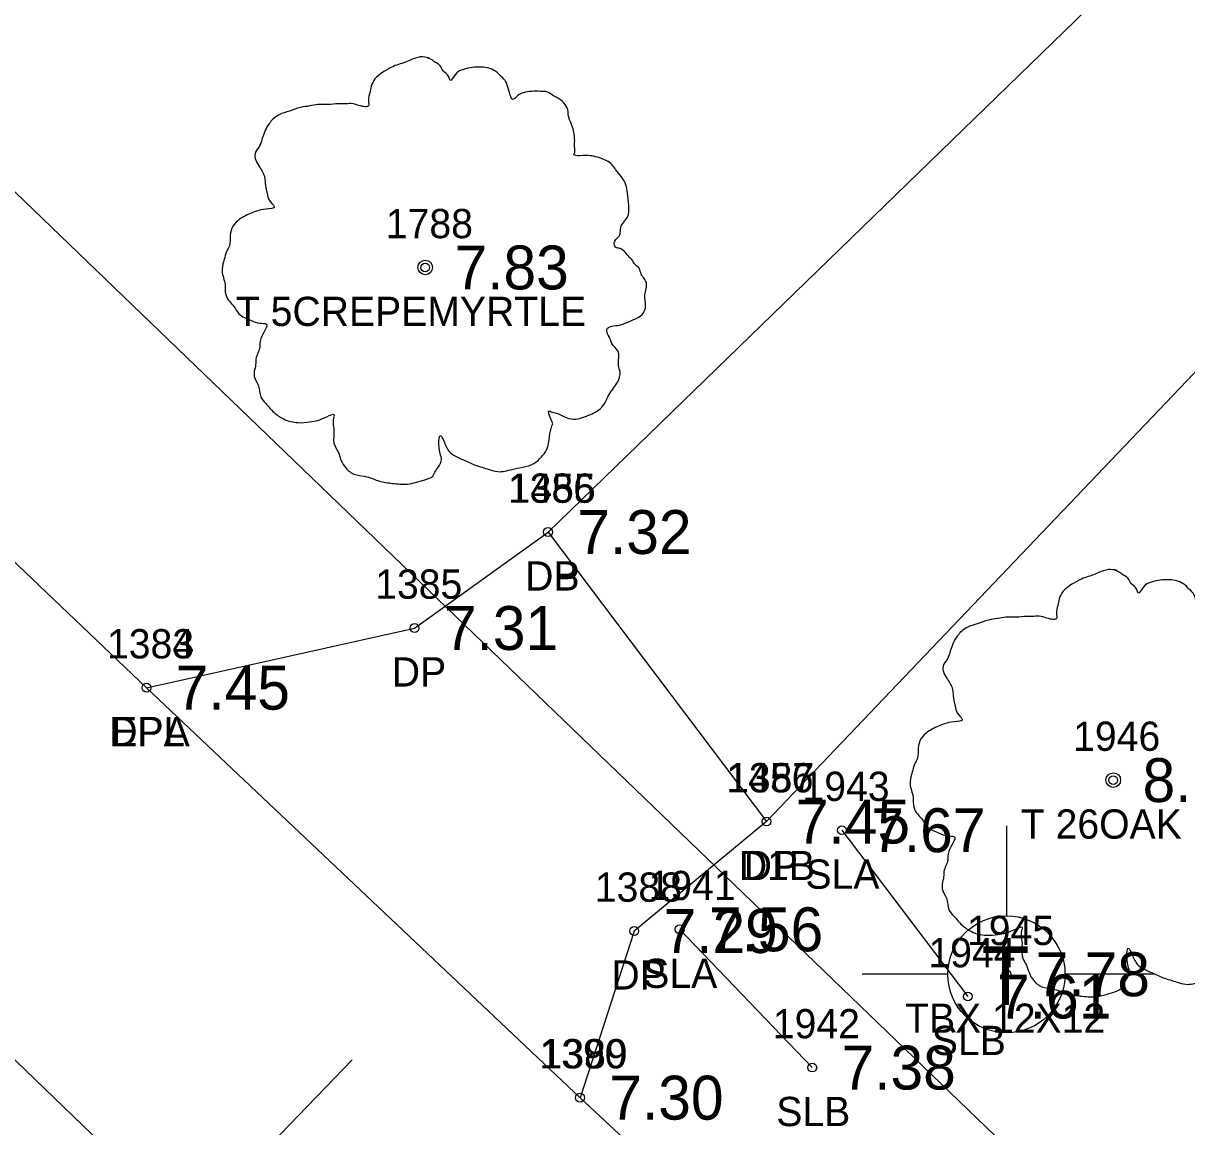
# Model space of a CAD drawing. Extents: x 2608598 to 2610682, y 641451 to 643526.
# Drawn here: x 2609158.19 to 2609197.94, y 643040.35 to 643078.05 of the extents above; entities that cross this region are included whole.
import ezdxf

# ---------------------------------------------------------------- set-up
doc = ezdxf.new("R2010")
doc.units = 0
for name, color, linetype in [('RD_EX_DR_Pipe', 7, 'Continuous'), ('RD_EX_Driveway', 7, 'Continuous'), ('RD_EX_Driveway_txCode', 7, 'Continuous'), ('RD_EX_Road', 7, 'Continuous'), ('RD_EX_Road_txCode', 7, 'Continuous'), ('RD_EX_TX_Driveway_ELEV', 7, 'Continuous'), ('RD_EX_TX_Road_ELEV', 7, 'Continuous'), ('RD_EX_TX_UT_ELEV', 7, 'Continuous'), ('RD_EX_TX_VEG_ELEV', 7, 'Continuous'), ('RD_EX_UT', 7, 'Continuous'), ('RD_EX_UT_txCode', 7, 'Continuous'), ('RD_EX_VEG', 7, 'Continuous'), ('RD_EX_VEG_txCode', 7, 'Continuous'), ('RD_HC_Cl', 7, 'Continuous'), ('RD_HC_Data_Tic', 7, 'Continuous'), ('RD_SMD_Locator', 7, 'Continuous')]:
    doc.layers.add(name, color=color, linetype=linetype)

msp = doc.modelspace()

# ---------------------------------------------------------------- linework, layer by layer
at = {"layer": 'RD_EX_DR_Pipe'}
msp.add_line((2609069.044, 643157.849), (2609202.653, 643029.203), dxfattribs=at)
at = {"layer": 'RD_EX_Driveway'}
for points in [[(2609166.457, 643161.041), (2609160.17, 643148.257), (2609190.362, 643122.83), (2609213.317, 643102.873), (2609223.768, 643094.8), (2609208.755, 643077.174), (2609183.581, 643050.775)], [(2609100.57, 643145.923), (2609122.94, 643140.66), (2609155.044, 643137.099), (2609182.051, 643117.558), (2609202.041, 643097.354), (2609199.499, 643083.361), (2609176.116, 643060.669)], [(2609162.396, 643055.351), (2609171.558, 643057.39), (2609176.116, 643060.669), (2609183.581, 643050.775), (2609179.063, 643047.036), (2609177.209, 643041.342)]]:
    msp.add_lwpolyline(points, dxfattribs=at)
at = {"layer": 'RD_EX_Road'}
msp.add_lwpolyline([(2609042.495, 643170.94), (2609058.512, 643155.458), (2609096.06, 643119.372), (2609116.51, 643099.11), (2609162.396, 643055.351), (2609177.209, 643041.342), (2609188.353, 643030.959), (2609199.912, 643019.764), (2609205.803, 643014.044), (2609217.132, 643003.172), (2609235.835, 642983.899), (2609237.032, 642983.51), (2609256.803, 642965.042), (2609258.491, 642962.514), (2609263.653, 642957.664), (2609344.713, 642879.888)], dxfattribs=at)
at = {"layer": 'RD_EX_UT'}
for p, q in [((2609191.777, 643050.627), (2609191.777, 643047.558)), ((2609186.847, 643045.573), (2609189.777, 643045.573)), ((2609193.777, 643045.573), (2609196.847, 643045.573))]:
    msp.add_line(p, q, dxfattribs=at)
msp.add_circle((2609191.777, 643045.558), 2, dxfattribs=at)
at = {"layer": 'RD_EX_VEG'}
for p, q in [((2609186.156, 643050.481), (2609190.458, 643044.797)), ((2609180.614, 643047.093), (2609185.144, 643042.37))]:
    msp.add_line(p, q, dxfattribs=at)
for centre, radius in [((2609171.922, 643069.709), 0.25), ((2609171.909, 643069.69), 0.0001), ((2609195.426, 643052.193), 0.25), ((2609195.413, 643052.174), 0.0001)]:
    msp.add_circle(centre, radius, dxfattribs=at)
for points in [[(2609172.054, 643076.876), (2609171.754, 643076.901), (2609171.429, 643076.801), (2609171.179, 643076.702), (2609170.954, 643076.627), (2609170.729, 643076.527), (2609170.43, 643076.352), (2609170.205, 643076.152), (2609170.08, 643075.902), (2609170.03, 643075.677), (2609169.98, 643075.402), (2609169.98, 643075.227), (2609169.855, 643075.202), (2609169.705, 643075.227), (2609169.455, 643075.302), (2609169.205, 643075.302), (2609168.955, 643075.302), (2609168.605, 643075.277), (2609168.256, 643075.277), (2609167.981, 643075.227), (2609167.656, 643075.177), (2609167.281, 643075.052), (2609166.931, 643074.927), (2609166.631, 643074.677), (2609166.381, 643074.203), (2609166.256, 643073.853), (2609166.107, 643073.603), (2609166.256, 643073.153), (2609166.431, 643072.803), (2609166.456, 643072.603), (2609166.531, 643072.179), (2609166.631, 643071.954), (2609166.756, 643071.754), (2609166.681, 643071.729), (2609166.306, 643071.679), (2609166.007, 643071.579), (2609165.582, 643071.354), (2609165.357, 643071.129), (2609165.257, 643070.804), (2609165.232, 643070.454), (2609165.132, 643070.254), (2609165.057, 643069.979), (2609165.032, 643069.904), (2609164.982, 643069.58), (2609165.082, 643069.13), (2609165.107, 643068.78), (2609165.232, 643068.555), (2609165.382, 643068.38), (2609165.557, 643068.13), (2609165.957, 643067.905), (2609166.281, 643067.805), (2609166.481, 643067.78), (2609166.306, 643067.281), (2609166.256, 643066.931), (2609166.132, 643066.531), (2609166.132, 643066.456), (2609166.082, 643065.981), (2609166.231, 643065.656), (2609166.306, 643065.282), (2609166.481, 643065.057), (2609166.756, 643064.757), (2609167.081, 643064.532), (2609167.581, 643064.407), (2609167.981, 643064.432), (2609168.556, 643064.607), (2609168.805, 643064.682), (2609168.78, 643064.507), (2609168.805, 643064.132), (2609168.805, 643063.707), (2609168.955, 643063.382), (2609169.055, 643063.107), (2609169.205, 643062.858), (2609169.53, 643062.633), (2609169.93, 643062.558), (2609170.355, 643062.408), (2609170.805, 643062.333), (2609171.304, 643062.308), (2609171.904, 643062.458), (2609172.179, 643062.583), (2609172.279, 643062.758), (2609172.479, 643063.132), (2609172.429, 643063.357), (2609172.454, 643063.957), (2609172.554, 643063.782), (2609172.729, 643063.432), (2609173.228, 643063.132), (2609173.628, 643062.958), (2609174.103, 643062.808), (2609174.403, 643062.733), (2609174.878, 643062.808), (2609175.253, 643062.883), (2609175.627, 643063.008), (2609175.927, 643063.282), (2609176.102, 643063.557), (2609176.152, 643063.832), (2609176.227, 643064.207), (2609176.277, 643064.382)], [(2609176.277, 643064.382), (2609176.202, 643064.557), (2609176.152, 643064.807), (2609176.227, 643064.782), (2609176.402, 643064.732), (2609176.677, 643064.607), (2609176.902, 643064.532), (2609177.227, 643064.557), (2609177.502, 643064.657), (2609177.951, 643064.932), (2609178.226, 643065.406), (2609178.501, 643065.806), (2609178.576, 643066.131), (2609178.526, 643066.356), (2609178.501, 643066.856), (2609178.301, 643067.106), (2609178.251, 643067.231), (2609178.151, 643067.63), (2609178.226, 643067.68), (2609178.501, 643067.73), (2609178.876, 643067.855), (2609179.151, 643067.98), (2609179.376, 643068.155), (2609179.451, 643068.38), (2609179.426, 643068.78), (2609179.476, 643069.18), (2609179.401, 643069.33), (2609179.301, 643069.48), (2609179.226, 643069.68), (2609179.076, 643069.829), (2609178.976, 643069.979), (2609178.876, 643070.079), (2609178.751, 643070.229), (2609178.576, 643070.354), (2609178.426, 643070.404), (2609178.376, 643070.554), (2609178.526, 643070.754), (2609178.576, 643070.854), (2609178.601, 643071.079), (2609178.826, 643071.429), (2609178.876, 643071.829), (2609178.826, 643072.253), (2609178.776, 643072.528), (2609178.626, 643072.803), (2609178.426, 643073.053), (2609178.301, 643073.228), (2609178.126, 643073.353), (2609177.801, 643073.478), (2609177.552, 643073.528), (2609177.202, 643073.528), (2609177.002, 643073.578), (2609177.027, 643073.628), (2609177.027, 643073.778), (2609177.027, 643074.053), (2609176.952, 643074.502), (2609176.802, 643075.002), (2609176.802, 643075.027), (2609176.702, 643075.277), (2609176.477, 643075.477), (2609176.302, 643075.577), (2609176.102, 643075.702), (2609175.852, 643075.727), (2609175.552, 643075.727), (2609175.277, 643075.677), (2609175.078, 643075.577), (2609174.903, 643075.452), (2609174.828, 643075.602), (2609174.728, 643075.902), (2609174.678, 643076.052), (2609174.528, 643076.227), (2609174.303, 643076.427), (2609173.853, 643076.552), (2609173.228, 643076.477), (2609172.928, 643076.277), (2609172.779, 643076.102), (2609172.729, 643076.227), (2609172.529, 643076.427), (2609172.429, 643076.602), (2609172.254, 643076.727), (2609172.104, 643076.826), (2609172.004, 643076.876)], [(2609195.557, 643059.36), (2609195.258, 643059.385), (2609194.933, 643059.285), (2609194.683, 643059.185), (2609194.458, 643059.11), (2609194.233, 643059.01), (2609193.933, 643058.835), (2609193.708, 643058.635), (2609193.583, 643058.386), (2609193.533, 643058.161), (2609193.483, 643057.886), (2609193.483, 643057.711), (2609193.358, 643057.686), (2609193.208, 643057.711), (2609192.959, 643057.786), (2609192.709, 643057.786), (2609192.459, 643057.786), (2609192.109, 643057.761), (2609191.759, 643057.761), (2609191.484, 643057.711), (2609191.159, 643057.661), (2609190.785, 643057.536), (2609190.435, 643057.411), (2609190.135, 643057.161), (2609189.885, 643056.686), (2609189.76, 643056.336), (2609189.61, 643056.087), (2609189.76, 643055.637), (2609189.935, 643055.287), (2609189.96, 643055.087), (2609190.035, 643054.662), (2609190.135, 643054.437), (2609190.26, 643054.237), (2609190.185, 643054.212), (2609189.81, 643054.162), (2609189.51, 643054.062), (2609189.085, 643053.838), (2609188.86, 643053.613), (2609188.76, 643053.288), (2609188.735, 643052.938), (2609188.636, 643052.738), (2609188.561, 643052.463), (2609188.536, 643052.388), (2609188.486, 643052.063), (2609188.586, 643051.613), (2609188.611, 643051.264), (2609188.735, 643051.039), (2609188.885, 643050.864), (2609189.06, 643050.614), (2609189.46, 643050.389), (2609189.785, 643050.289), (2609189.985, 643050.264), (2609189.81, 643049.764), (2609189.76, 643049.414), (2609189.635, 643049.015), (2609189.635, 643048.94), (2609189.585, 643048.465), (2609189.735, 643048.14), (2609189.81, 643047.765), (2609189.985, 643047.54), (2609190.26, 643047.24), (2609190.585, 643047.016), (2609191.084, 643046.891), (2609191.484, 643046.916), (2609192.059, 643047.09), (2609192.309, 643047.165), (2609192.284, 643046.991), (2609192.309, 643046.616), (2609192.309, 643046.191), (2609192.459, 643045.866), (2609192.559, 643045.591), (2609192.709, 643045.341), (2609193.034, 643045.116), (2609193.433, 643045.041), (2609193.858, 643044.891), (2609194.308, 643044.816), (2609194.808, 643044.791), (2609195.408, 643044.941), (2609195.682, 643045.066), (2609195.782, 643045.241), (2609195.982, 643045.616), (2609195.932, 643045.841), (2609195.957, 643046.441), (2609196.057, 643046.266), (2609196.232, 643045.916), (2609196.732, 643045.616), (2609197.132, 643045.441), (2609197.607, 643045.291), (2609197.906, 643045.216), (2609198.381, 643045.291), (2609198.756, 643045.366), (2609199.131, 643045.491), (2609199.431, 643045.766), (2609199.606, 643046.041), (2609199.656, 643046.316), (2609199.731, 643046.691), (2609199.781, 643046.866)], [(2609199.781, 643046.866), (2609199.706, 643047.041), (2609199.656, 643047.29), (2609199.731, 643047.265), (2609199.906, 643047.215), (2609200.18, 643047.09), (2609200.405, 643047.016), (2609200.73, 643047.041), (2609201.005, 643047.14), (2609201.455, 643047.415), (2609201.73, 643047.89), (2609202.005, 643048.29), (2609202.08, 643048.615), (2609202.03, 643048.84), (2609202.005, 643049.339), (2609201.805, 643049.589), (2609201.755, 643049.714), (2609201.655, 643050.114), (2609201.73, 643050.164), (2609202.005, 643050.214), (2609202.379, 643050.339), (2609202.654, 643050.464), (2609202.879, 643050.639), (2609202.954, 643050.864), (2609202.929, 643051.264), (2609202.979, 643051.663), (2609202.904, 643051.813), (2609202.804, 643051.963), (2609202.729, 643052.163), (2609202.579, 643052.313), (2609202.479, 643052.463), (2609202.379, 643052.563), (2609202.255, 643052.713), (2609202.08, 643052.838), (2609201.93, 643052.888), (2609201.88, 643053.038), (2609202.03, 643053.238), (2609202.08, 643053.338), (2609202.105, 643053.563), (2609202.33, 643053.912), (2609202.379, 643054.312), (2609202.33, 643054.737), (2609202.28, 643055.012), (2609202.13, 643055.287), (2609201.93, 643055.537), (2609201.805, 643055.712), (2609201.63, 643055.837), (2609201.305, 643055.962), (2609201.055, 643056.012), (2609200.705, 643056.012), (2609200.505, 643056.062), (2609200.53, 643056.112), (2609200.53, 643056.261), (2609200.53, 643056.536), (2609200.455, 643056.986), (2609200.305, 643057.486), (2609200.305, 643057.511), (2609200.205, 643057.761), (2609199.981, 643057.961), (2609199.806, 643058.061), (2609199.606, 643058.186), (2609199.356, 643058.211), (2609199.056, 643058.211), (2609198.781, 643058.161), (2609198.581, 643058.061), (2609198.406, 643057.936), (2609198.331, 643058.086), (2609198.231, 643058.386), (2609198.181, 643058.535), (2609198.031, 643058.71), (2609197.807, 643058.91), (2609197.357, 643059.035), (2609196.732, 643058.96), (2609196.432, 643058.76), (2609196.282, 643058.585), (2609196.232, 643058.71), (2609196.032, 643058.91), (2609195.932, 643059.085), (2609195.757, 643059.21), (2609195.607, 643059.31), (2609195.507, 643059.36)]]:
    msp.add_spline(points, degree=3, dxfattribs=at)
at = {"layer": 'RD_HC_Cl'}
msp.add_line((2608814.812, 643373.733), (2610092.394, 642140.787), dxfattribs=at)
at = {"layer": 'RD_HC_Data_Tic'}
msp.add_line((2609163.866, 643036.874), (2609169.421, 643042.631), dxfattribs=at)
at = {"layer": 'RD_SMD_Locator'}
for centre in [(2609171.922, 643069.709), (2609176.116, 643060.669), (2609176.116, 643060.669), (2609171.558, 643057.39), (2609162.396, 643055.351), (2609162.396, 643055.351), (2609195.426, 643052.193), (2609183.581, 643050.775), (2609183.581, 643050.775), (2609186.156, 643050.481), (2609179.063, 643047.036), (2609180.614, 643047.093), (2609191.777, 643045.558), (2609190.458, 643044.797), (2609185.144, 643042.37), (2609177.209, 643041.342), (2609177.209, 643041.342)]:
    msp.add_circle(centre, 0.15, dxfattribs=at)

# ---------------------------------------------------------------- texts
at = {"layer": 'RD_EX_Driveway_txCode'}
for s, p in [('1386', (2609174.746, 643061.669)), ('1455', (2609174.769, 643061.669)), ('DP', (2609175.336, 643058.669)), ('DB', (2609175.336, 643058.669)), ('1385', (2609170.212, 643058.39)), ('1384', (2609161.05, 643056.351)), ('DP', (2609170.779, 643055.39)), ('DPA', (2609161.128, 643053.351)), ('1456', (2609182.21, 643051.775)), ('1387', (2609182.234, 643051.775)), ('D1B', (2609182.636, 643048.775)), ('DP', (2609182.801, 643048.775)), ('1388', (2609177.716, 643048.036)), ('DP', (2609178.283, 643045.036)), ('1389', (2609175.862, 643042.342))]:
    msp.add_text(s, height=1, dxfattribs=at).set_placement(p)
at = {"layer": 'RD_EX_Road_txCode'}
for s, p in [('1383', (2609161.05, 643056.351)), ('EPL', (2609161.191, 643053.351)), ('1390', (2609175.823, 643042.342))]:
    msp.add_text(s, height=1, dxfattribs=at).set_placement(p)
at = {"layer": 'RD_EX_TX_Driveway_ELEV'}
for s, p in [('7.32', (2609177.116, 643059.919)), ('7.32', (2609177.116, 643059.919)), ('7.31', (2609172.558, 643056.64)), ('7.45', (2609163.396, 643054.601)), ('7.45', (2609184.581, 643050.025)), ('7.45', (2609184.581, 643050.025)), ('7.29', (2609180.063, 643046.286)), ('7.30', (2609178.209, 643040.592))]:
    msp.add_text(s, height=1.5, dxfattribs=at).set_placement(p)
at = {"layer": 'RD_EX_TX_Road_ELEV'}
for s, p in [('7.45', (2609163.396, 643054.601)), ('7.30', (2609178.209, 643040.592))]:
    msp.add_text(s, height=1.5, dxfattribs=at).set_placement(p)
at = {"layer": 'RD_EX_TX_UT_ELEV'}
msp.add_text('7.78', height=1.5, dxfattribs=at).set_placement((2609192.777, 643044.808))
at = {"layer": 'RD_EX_TX_VEG_ELEV'}
for s, p in [('7.83', (2609172.922, 643068.959)), ('8.14', (2609196.426, 643051.443)), ('7.67', (2609187.156, 643049.731)), ('7.56', (2609181.614, 643046.343)), ('7.61', (2609191.458, 643044.047)), ('7.38', (2609186.144, 643041.62))]:
    msp.add_text(s, height=1.5, dxfattribs=at).set_placement(p)
at = {"layer": 'RD_EX_UT'}
msp.add_text('T', height=2, dxfattribs=at).set_placement((2609190.928, 643044.51))
at = {"layer": 'RD_EX_UT_txCode'}
for s, p in [('1945', (2609190.431, 643046.558)), ('TBX 12X12', (2609188.313, 643043.558))]:
    msp.add_text(s, height=1, dxfattribs=at).set_placement(p)
at = {"layer": 'RD_EX_VEG_txCode'}
for s, p in [('1788', (2609170.576, 643070.709)), ('T 5CREPEMYRTLE', (2609165.453, 643067.709)), ('1946', (2609194.055, 643053.193)), ('1943', (2609184.81, 643051.481)), ('T 26OAK', (2609192.268, 643050.193)), ('SLA', (2609184.912, 643048.481)), ('1941', (2609179.551, 643048.093)), ('1944', (2609189.111, 643045.797)), ('SLA', (2609179.37, 643045.093)), ('1942', (2609183.797, 643043.37)), ('SLB', (2609189.229, 643042.797)), ('SLB', (2609183.915, 643040.37))]:
    msp.add_text(s, height=1, dxfattribs=at).set_placement(p)

doc.saveas('drawing.dxf')
